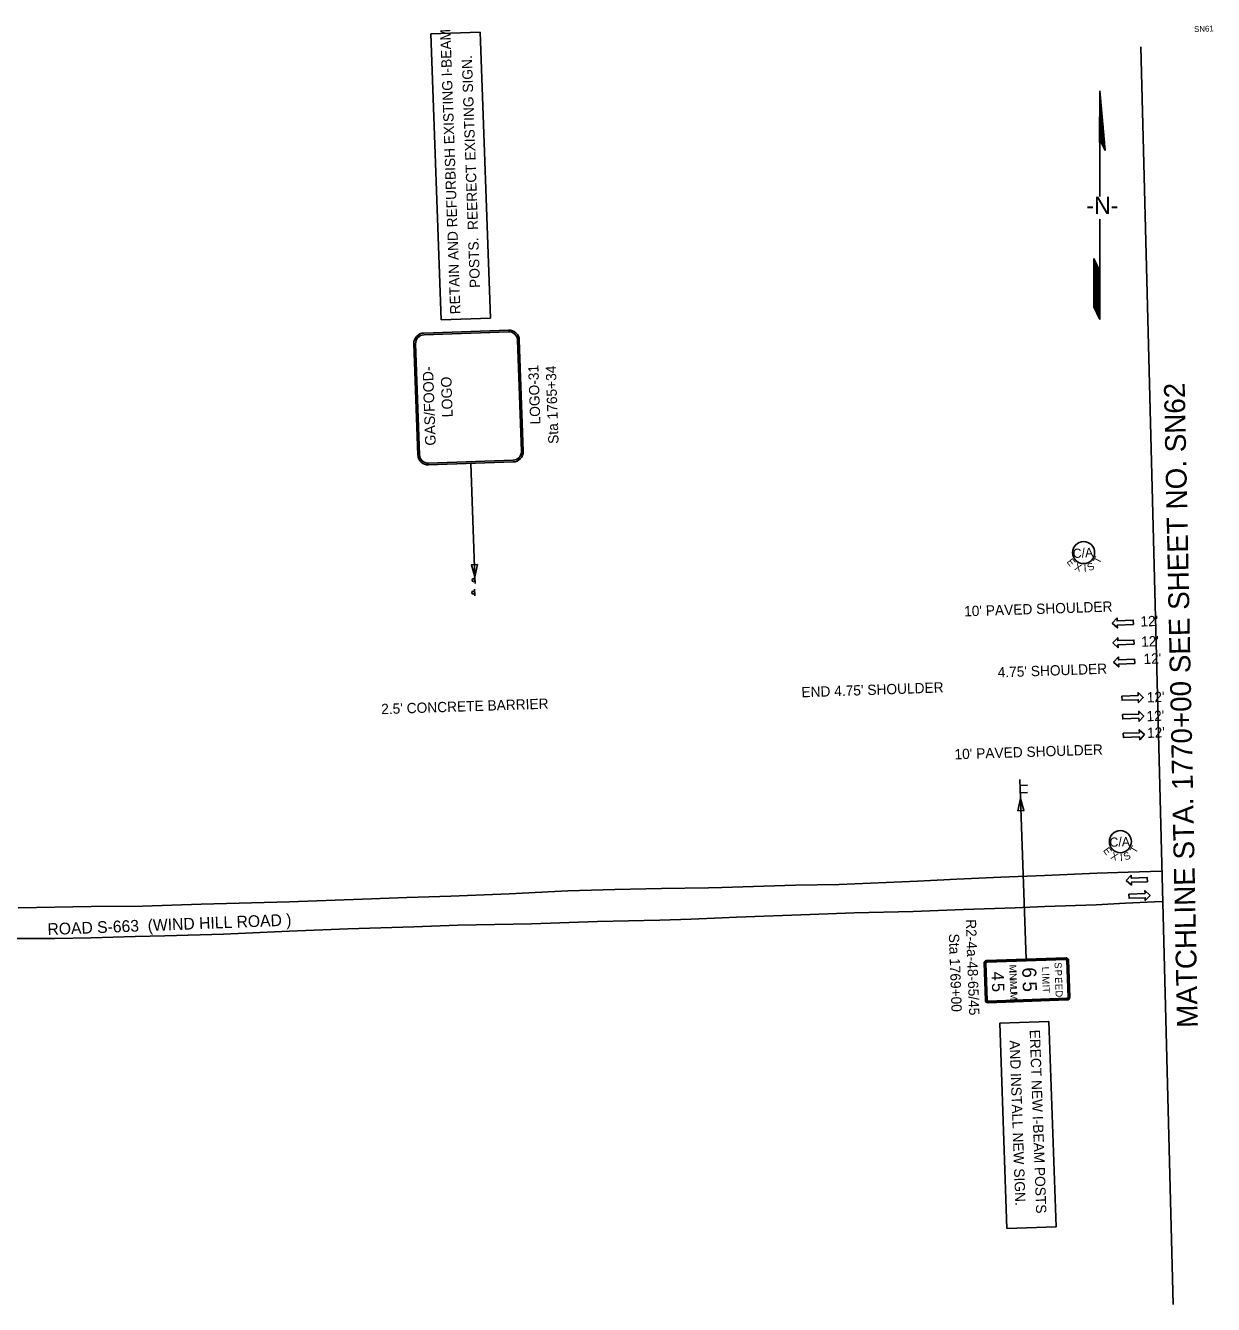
# Model space of a CAD drawing. Extents: x 1821945 to 1823510, y 1192489 to 1193361.
# Drawn here: x 1822700 to 1823510, y 1192489 to 1193361 of the extents above; entities that cross this region are included whole.
import ezdxf

# ---------------------------------------------------------------- set-up
doc = ezdxf.new("R2010")
doc.units = 0
for name, color, linetype in [('RD_EX_Road', 7, 'Continuous'), ('RD_PD_Final_LnLine', 7, 'Continuous'), ('RD_PD_Final_TX', 7, 'Continuous'), ('RD_SHT_MatchLine', 7, 'Continuous'), ('RD_SHT_TX', 7, 'Continuous'), ('RD_Sketch1', 7, 'Continuous'), ('RD_Sketch8', 7, 'Continuous'), ('RD_TX_RoadID', 7, 'Continuous'), ('SN_P_Signs', 7, 'Continuous')]:
    doc.layers.add(name, color=color, linetype=linetype)

# ---------------------------------------------------------------- blocks, each defined once
blk = doc.blocks.new('SARRW2')
at = {"layer": 'RD_PD_Final_LnLine'}
blk.add_lwpolyline([(-12, 1.2), (-12, -1.2), (-2.83, -1.2), (-2.83, -2.83), (0, 0), (-2.83, 2.83), (-2.83, 1.2)], close=True, dxfattribs=at)

msp = doc.modelspace()

# ---------------------------------------------------------------- linework, layer by layer
at = {"layer": 'RD_EX_Road'}
for points in [[(1823475.25, 1192784.82), (1823452.24, 1192784.09), (1823431.14, 1192783.3), (1823395.17, 1192781.83), (1823365.32, 1192780.6), (1823335.33, 1192779.23), (1823308.48, 1192777.96), (1823255.21, 1192775.68), (1823225.28, 1192775.13), (1823175.2, 1192773.52), (1823166.08, 1192773.41), (1823134.12, 1192772.88), (1823102.16, 1192772.15), (1823070.2, 1192771.23), (1823030.23, 1192769.23), (1822990.38, 1192767.7), (1822960.43, 1192766.88), (1822930.07, 1192765.68), (1822880.29, 1192763.91), (1822820.21, 1192762.13), (1822780.21, 1192760.86), (1822745.23, 1192760.53), (1822695.39, 1192759.67)], [(1823475.78, 1192764.01), (1823470.24, 1192763.82), (1823450.26, 1192762.95), (1823430.29, 1192761.88), (1823395.27, 1192760.62), (1823375.1, 1192759.7), (1823339.91, 1192758.49), (1823305.49, 1192757.24), (1823265.31, 1192756.25), (1823235.35, 1192755.18), (1823185.19, 1192753.48), (1823175.41, 1192753), (1823154.14, 1192752.08), (1823132.87, 1192751.36), (1823111.58, 1192750.84), (1823090.3, 1192750.51), (1823045.31, 1192748.81), (1822995.17, 1192748), (1822965.11, 1192746.85), (1822920.18, 1192745.35), (1822880.06, 1192743.74), (1822835.35, 1192741.74), (1822795.29, 1192740.6), (1822775.17, 1192740.19), (1822745.25, 1192739.32), (1822720.39, 1192738.89), (1822690.27, 1192738.86)]]:
    msp.add_lwpolyline(points, dxfattribs=at)
at = {"layer": 'RD_SHT_MatchLine'}
msp.add_lwpolyline([(1823460.85, 1193346.63), (1823482.82, 1192489.43)], dxfattribs=at)
at = {"layer": 'RD_Sketch1'}
for p, q in [((1823432.85, 1193316.6), (1823432.64, 1193281.44)), ((1823436.57, 1193275.9), (1823432.85, 1193316.6)), ((1823433.15, 1193282.84), (1823436.57, 1193275.9)), ((1823432.85, 1193281.73), (1823432.85, 1193259.91)), ((1823432.85, 1193259.91), (1823432.85, 1193244.44)), ((1823432.85, 1193228.99), (1823432.85, 1193203.22)), ((1823428.85, 1193188.16), (1823428.85, 1193202.33)), ((1823428.85, 1193202.33), (1823432.85, 1193193.77)), ((1823432.85, 1193203.22), (1823432.85, 1193160.7)), ((1823428.85, 1193169.26), (1823428.85, 1193188.16)), ((1823432.85, 1193160.7), (1823428.85, 1193169.26))]:
    msp.add_line(p, q, dxfattribs=at)
for points in [[(1823432.86, 1193282.04), (1823432.86, 1193316.48)], [(1823432.95, 1193282.3), (1823432.95, 1193315.45)], [(1823433.05, 1193282.56), (1823433.05, 1193314.41)], [(1823433.14, 1193282.82), (1823433.14, 1193313.38)], [(1823433.24, 1193282.67), (1823433.24, 1193312.35)], [(1823433.33, 1193282.47), (1823433.33, 1193311.32)], [(1823433.42, 1193282.28), (1823433.42, 1193310.28)], [(1823433.52, 1193282.09), (1823433.52, 1193309.25)], [(1823432.76, 1193281.78), (1823432.76, 1193302.56)], [(1823433.61, 1193281.9), (1823433.61, 1193308.22)], [(1823433.71, 1193281.71), (1823433.71, 1193307.19)], [(1823433.8, 1193281.52), (1823433.8, 1193306.15)], [(1823433.9, 1193281.32), (1823433.9, 1193305.12)], [(1823433.99, 1193281.13), (1823433.99, 1193304.09)], [(1823434.09, 1193280.94), (1823434.09, 1193303.06)], [(1823434.18, 1193280.75), (1823434.18, 1193302.02)], [(1823434.27, 1193280.56), (1823434.27, 1193300.99)], [(1823434.37, 1193280.37), (1823434.37, 1193299.96)], [(1823434.46, 1193280.17), (1823434.46, 1193298.93)], [(1823434.56, 1193279.98), (1823434.56, 1193297.89)], [(1823434.65, 1193279.79), (1823434.65, 1193296.86)], [(1823434.75, 1193279.6), (1823434.75, 1193295.83)], [(1823434.84, 1193279.41), (1823434.84, 1193294.8)], [(1823434.94, 1193279.22), (1823434.94, 1193293.76)], [(1823435.03, 1193279.02), (1823435.03, 1193292.73)], [(1823435.13, 1193278.83), (1823435.13, 1193291.7)], [(1823432.67, 1193281.52), (1823432.67, 1193286.66)], [(1823435.22, 1193278.64), (1823435.22, 1193290.67)], [(1823435.31, 1193278.45), (1823435.31, 1193289.63)], [(1823435.41, 1193278.26), (1823435.41, 1193288.6)], [(1823435.5, 1193278.06), (1823435.5, 1193287.57)], [(1823435.6, 1193277.87), (1823435.6, 1193286.54)], [(1823435.69, 1193277.68), (1823435.69, 1193285.5)], [(1823435.79, 1193277.49), (1823435.79, 1193284.47)], [(1823435.88, 1193277.3), (1823435.88, 1193283.44)], [(1823435.98, 1193277.11), (1823435.98, 1193282.41)], [(1823436.07, 1193276.91), (1823436.07, 1193281.37)], [(1823436.16, 1193276.72), (1823436.16, 1193280.34)], [(1823436.26, 1193276.53), (1823436.26, 1193279.31)], [(1823436.35, 1193276.34), (1823436.35, 1193278.28)], [(1823436.45, 1193276.15), (1823436.45, 1193277.24)], [(1823436.54, 1193275.96), (1823436.54, 1193276.21)], [(1823428.93, 1193169.09), (1823428.93, 1193202.16)], [(1823429.02, 1193168.89), (1823429.02, 1193201.96)], [(1823429.12, 1193168.69), (1823429.12, 1193201.76)], [(1823429.21, 1193168.49), (1823429.21, 1193201.56)], [(1823429.31, 1193168.28), (1823429.31, 1193201.35)], [(1823429.4, 1193168.08), (1823429.4, 1193201.15)], [(1823429.5, 1193167.88), (1823429.5, 1193200.95)], [(1823429.59, 1193167.68), (1823429.59, 1193200.75)], [(1823429.69, 1193167.47), (1823429.69, 1193200.54)], [(1823429.78, 1193167.27), (1823429.78, 1193200.34)], [(1823429.88, 1193167.07), (1823429.88, 1193200.14)], [(1823429.97, 1193166.87), (1823429.97, 1193199.94)], [(1823430.06, 1193166.66), (1823430.06, 1193199.73)], [(1823430.16, 1193166.46), (1823430.16, 1193199.53)], [(1823430.25, 1193166.26), (1823430.25, 1193199.33)], [(1823430.35, 1193166.05), (1823430.35, 1193199.13)], [(1823430.44, 1193165.85), (1823430.44, 1193198.92)], [(1823430.54, 1193165.65), (1823430.54, 1193198.72)], [(1823430.63, 1193165.45), (1823430.63, 1193198.52)], [(1823430.73, 1193165.24), (1823430.73, 1193198.31)], [(1823430.82, 1193165.04), (1823430.82, 1193198.11)], [(1823430.91, 1193164.84), (1823430.91, 1193197.91)], [(1823431.01, 1193164.64), (1823431.01, 1193197.71)], [(1823431.1, 1193164.43), (1823431.1, 1193197.5)], [(1823431.2, 1193164.23), (1823431.2, 1193197.3)], [(1823431.29, 1193164.03), (1823431.29, 1193197.1)], [(1823431.39, 1193163.83), (1823431.39, 1193196.9)], [(1823431.48, 1193163.62), (1823431.48, 1193196.69)], [(1823431.58, 1193163.42), (1823431.58, 1193196.49)], [(1823431.67, 1193163.22), (1823431.67, 1193196.29)], [(1823431.76, 1193163.02), (1823431.76, 1193196.09)], [(1823431.86, 1193162.81), (1823431.86, 1193195.88)], [(1823431.95, 1193162.61), (1823431.95, 1193195.68)], [(1823432.05, 1193162.41), (1823432.05, 1193195.48)], [(1823432.14, 1193162.2), (1823432.14, 1193195.28)], [(1823432.24, 1193162), (1823432.24, 1193195.07)], [(1823432.33, 1193161.8), (1823432.33, 1193194.87)], [(1823432.43, 1193161.6), (1823432.43, 1193194.67)], [(1823432.52, 1193161.39), (1823432.52, 1193194.46)], [(1823432.62, 1193161.19), (1823432.62, 1193194.26)], [(1823432.71, 1193160.99), (1823432.71, 1193194.06)], [(1823432.8, 1193160.79), (1823432.8, 1193193.86)]]:
    msp.add_lwpolyline(points, dxfattribs=at)
at = {"layer": 'RD_Sketch8'}
for centre in [(1823421.8, 1193001.85), (1823446.87, 1192804.83)]:
    msp.add_circle(centre, 7.5, dxfattribs=at)
at = {"layer": 'SN_P_Signs'}
for p, q in [((1822976.84, 1193355.35), (1823010.44, 1193356.54)), ((1822983.75, 1193160.45), (1822976.84, 1193355.35)), ((1823010.44, 1193356.54), (1823017.35, 1193161.65)), ((1823017.35, 1193161.65), (1822983.75, 1193160.45)), ((1823004.04, 1193062.58), (1823006.78, 1192985.37)), ((1823006.94, 1192980.87), (1823006.78, 1192985.37)), ((1823006.73, 1192972.39), (1823006.58, 1192976.89)), ((1823378.78, 1192834.2), (1823378.32, 1192847.23)), ((1823378.47, 1192843.12), (1823383.46, 1192843.3)), ((1823378.65, 1192838.11), (1823383.63, 1192838.28)), ((1823378.78, 1192834.2), (1823382.67, 1192724.75)), ((1823355.68, 1192723.8), (1823409.65, 1192725.71)), ((1823354.84, 1192696.75), (1823353.95, 1192721.93)), ((1823411.51, 1192723.98), (1823412.41, 1192698.79)), ((1823410.67, 1192696.93), (1823356.7, 1192695.01)), ((1823364.6, 1192681.06), (1823398.2, 1192682.26)), ((1823369.57, 1192541.13), (1823364.6, 1192681.06)), ((1823398.2, 1192682.26), (1823403.16, 1192542.32)), ((1823403.16, 1192542.32), (1823369.57, 1192541.13))]:
    msp.add_line(p, q, dxfattribs=at)
for points in [[(1822972.07, 1193151.51), (1823029.63, 1193153.55)], [(1822972.11, 1193150.31), (1823029.68, 1193152.35)], [(1822967.81, 1193068.5), (1822965.13, 1193144.05)], [(1822969.01, 1193068.54), (1822966.33, 1193144.1)], [(1823035.89, 1193146.56), (1823038.57, 1193071.01)], [(1823037.08, 1193146.61), (1823039.76, 1193071.05)], [(1823032.78, 1193064.8), (1822975.22, 1193062.76)], [(1823032.82, 1193063.6), (1822975.26, 1193061.56)], [(1823355.7, 1192723.35), (1823409.67, 1192725.26)], [(1823355.29, 1192696.77), (1823354.4, 1192721.95)], [(1823356.04, 1192696.79), (1823355.15, 1192721.98)], [(1823355.73, 1192722.6), (1823409.69, 1192724.51)], [(1823410.31, 1192723.93), (1823411.21, 1192698.75)], [(1823411.06, 1192723.96), (1823411.96, 1192698.78)], [(1823410.63, 1192698.13), (1823356.66, 1192696.21)], [(1823410.65, 1192697.38), (1823356.69, 1192695.46)]]:
    msp.add_lwpolyline(points, dxfattribs=at)
for points in [[(1823008.54, 1192993.64), (1823006.78, 1192985.37), (1823004.44, 1192993.49)], [(1823377.03, 1192825.93), (1823378.78, 1192834.2), (1823381.12, 1192826.07)]]:
    msp.add_lwpolyline(points, close=True, dxfattribs=at)
for centre in [(1823005.85, 1192983.09), (1823005.64, 1192974.61)]:
    msp.add_circle(centre, 1, dxfattribs=at)
for centre, radius, start, end in [((1823029.89, 1193146.35), 7.2, 2.03127, 92.03127), ((1823029.89, 1193146.35), 6, 2.03127, 92.03127), ((1822972.33, 1193144.31), 7.2, 92.03127, 182.03127), ((1822972.33, 1193144.31), 6, 92.03127, 182.03127), ((1822975, 1193068.76), 7.2, 182.03127, 272.03127), ((1822975, 1193068.76), 6, 182.03127, 272.03127), ((1823032.57, 1193070.8), 6, 272.03127, 2.03127), ((1823032.57, 1193070.8), 7.2, 272.03127, 2.03127), ((1823409.71, 1192723.91), 1.8, 2.03127, 92.03127), ((1823409.71, 1192723.91), 1.35, 2.03127, 92.03127), ((1823355.75, 1192722), 1.8, 92.03127, 182.03127), ((1823355.75, 1192722), 1.35, 92.03127, 182.03127), ((1823355.75, 1192722), 0.6, 92.03127, 182.03127), ((1823409.71, 1192723.91), 0.6, 2.03127, 92.03127), ((1823410.61, 1192698.73), 0.6, 272.03127, 2.03127), ((1823410.61, 1192698.73), 1.35, 272.03127, 2.03127), ((1823410.61, 1192698.73), 1.8, 272.03127, 2.03127), ((1823356.64, 1192696.81), 1.8, 182.03127, 272.03127), ((1823356.64, 1192696.81), 1.35, 182.03127, 272.03127), ((1823356.64, 1192696.81), 0.6, 182.03127, 272.03127)]:
    msp.add_arc(centre, radius, start, end, dxfattribs=at)

# ---------------------------------------------------------------- block references
at = {"layer": 'RD_PD_Final_LnLine'}
for p, xscale, yscale, rotation in [((1823441.31, 1192953.76), 1.2000000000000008, 1.200000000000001, -177.99217052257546), ((1823441.78, 1192940.3), 1.2000000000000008, 1.200000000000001, -177.99217052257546), ((1823442.24, 1192927.2), 1.2000000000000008, 1.200000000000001, -177.99217052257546), ((1823462.42, 1192903.16), 1.200000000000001, 1.2000000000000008, 2.007829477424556), ((1823462.86, 1192890.47), 1.200000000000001, 1.2000000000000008, 2.007829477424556), ((1823463.31, 1192877.79), 1.200000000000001, 1.2000000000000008, 2.007829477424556), ((1823450.91, 1192778.46), 1.2000000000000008, 1.200000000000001, -177.99217052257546), ((1823467.15, 1192768.21), 1.200000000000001, 1.2000000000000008, 2.007829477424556)]:
    msp.add_blockref('SARRW2', p, dxfattribs=dict(at, xscale=xscale, yscale=yscale, rotation=rotation))

# ---------------------------------------------------------------- texts
at = {"layer": 'RD_PD_Final_TX'}
for s, rotation, p in [("10' PAVED SHOULDER", 1.88215, (1823340.45, 1192958.36)), ("12'", 2.21446, (1823460.67, 1192951.4)), ("12'", 2.21446, (1823461.15, 1192937.61)), ("4.75' SHOULDER", 2.00775, (1823363.34, 1192916.73)), ("12'", 2.21446, (1823462.76, 1192925.86)), ("END 4.75' SHOULDER", 2.00775, (1823229.53, 1192903.17)), ("2.5' CONCRETE BARRIER", 1.88215, (1822943, 1192891.71)), ("12'", 2.21446, (1823464.97, 1192899.66)), ("12'", 2.21446, (1823464.8, 1192886.83)), ("12'", 2.21446, (1823465.19, 1192875.49)), ("10' PAVED SHOULDER", 1.88215, (1823333.88, 1192860.9))]:
    msp.add_text(s, height=7, rotation=rotation, dxfattribs=at).set_placement(p)
at = {"layer": 'RD_SHT_TX'}
for s, height, rotation, p in [('SN61', 4, 2.03127, (1823497.21, 1193356.61)), ('MATCHLINE STA. 1770+00 SEE SHEET NO. SN62', 14.1726, 91.1747, (1823499.73, 1192678.08))]:
    msp.add_text(s, height=height, rotation=rotation, dxfattribs=at).set_placement(p)
at = {"layer": 'RD_Sketch1'}
msp.add_text('-N-', height=11.811, rotation=0, dxfattribs=at).set_placement((1823423.65, 1193232.7))
at = {"layer": 'RD_Sketch8'}
for s, height, rotation, p in [('C/A', 6.25, 4.02968, (1823414.63, 1192998.06)), ('E', 5, 307.24093, (1823410, 1192995.48)), ('X', 5, 339.6703, (1823415.16, 1192990.18)), ('S', 5, 25.82212, (1823425.7, 1192989.02)), ('T', 5, 62.21483, (1823432.58, 1192993.88)), ('I', 5, 3.8303, (1823422.07, 1192988.59)), ('C/A', 6.25, 2.00775, (1823439.58, 1192801.29)), ('E', 5, 305.21899, (1823434.85, 1192798.88)), ('X', 5, 337.64836, (1823439.83, 1192793.4)), ('I', 5, 1.80836, (1823446.68, 1192791.56)), ('S', 5, 23.80019, (1823450.32, 1192791.87)), ('T', 5, 60.19289, (1823457.36, 1192796.48))]:
    msp.add_text(s, height=height, rotation=rotation, dxfattribs=at).set_placement(p)
at = {"layer": 'RD_TX_RoadID'}
msp.add_text('ROAD S-663  (WIND HILL ROAD )', height=8, rotation=2.23942, dxfattribs=at).set_placement((1822715.53, 1192741.17))
at = {"layer": 'SN_P_Signs'}
for s, height, rotation, p in [('RETAIN AND REFURBISH EXISTING I-BEAM', 7, 92.03135, (1822996.98, 1193164.41)), ('POSTS.  REERECT EXISTING SIGN.', 7, 92.03135, (1823010.35, 1193182.36)), ('GAS/FOOD-', 7.2, 92.03127, (1822980.15, 1193074.86)), ('LOGO-31', 7, 92.03135, (1823051.5, 1193089.32)), ('Sta 1765+34', 7, 92.03135, (1823063.87, 1193076.08)), ('LOGO', 7.2, 92.03127, (1822991.71, 1193094.14)), ('R2-4a-48-65/45', 7, 272.03135, (1823341.46, 1192751.85)), ('Sta 1769+00', 7, 272.03135, (1823329.9, 1192742.01)), ('4', 8.4, 272.03127, (1823358.95, 1192716.2)), ('M', 4.8, 272.03127, (1823371.09, 1192720.94)), ('I', 4.8, 272.03127, (1823371.24, 1192716.82)), ('6', 9.6, 272.03127, (1823379.87, 1192719.04)), ('L', 4.8, 272.03127, (1823393.36, 1192719.52)), ('S', 4.8, 272.03127, (1823401.95, 1192722.59)), ('P', 4.8, 272.03127, (1823402.14, 1192717.5)), ('5', 8.4, 272.03127, (1823359.23, 1192708.46)), ('N', 4.8, 272.03127, (1823371.3, 1192715.14)), ('I', 4.8, 272.03127, (1823371.43, 1192711.5)), ('M', 4.8, 272.03127, (1823371.49, 1192709.82)), ('5', 9.6, 272.03127, (1823380.21, 1192709.42)), ('I', 4.8, 272.03127, (1823393.52, 1192715.01)), ('M', 4.8, 272.03127, (1823393.59, 1192712.95)), ('E', 4.8, 272.03127, (1823402.32, 1192712.4)), ('E', 4.8, 272.03127, (1823402.48, 1192707.86)), ('U', 4.8, 272.03127, (1823371.63, 1192705.7)), ('M', 4.8, 272.03127, (1823371.76, 1192702.06)), ('I', 4.8, 272.03127, (1823393.79, 1192707.29)), ('T', 4.8, 272.03127, (1823393.86, 1192705.47)), ('D', 4.8, 272.03127, (1823402.64, 1192703.32)), ('ERECT NEW I-BEAM POSTS', 6.9998, 272.03135, (1823385.03, 1192676.55)), ('AND INSTALL NEW SIGN.', 6.9998, 272.03135, (1823371.28, 1192669.37))]:
    msp.add_text(s, height=height, rotation=rotation, dxfattribs=at).set_placement(p)

doc.saveas('drawing.dxf')
